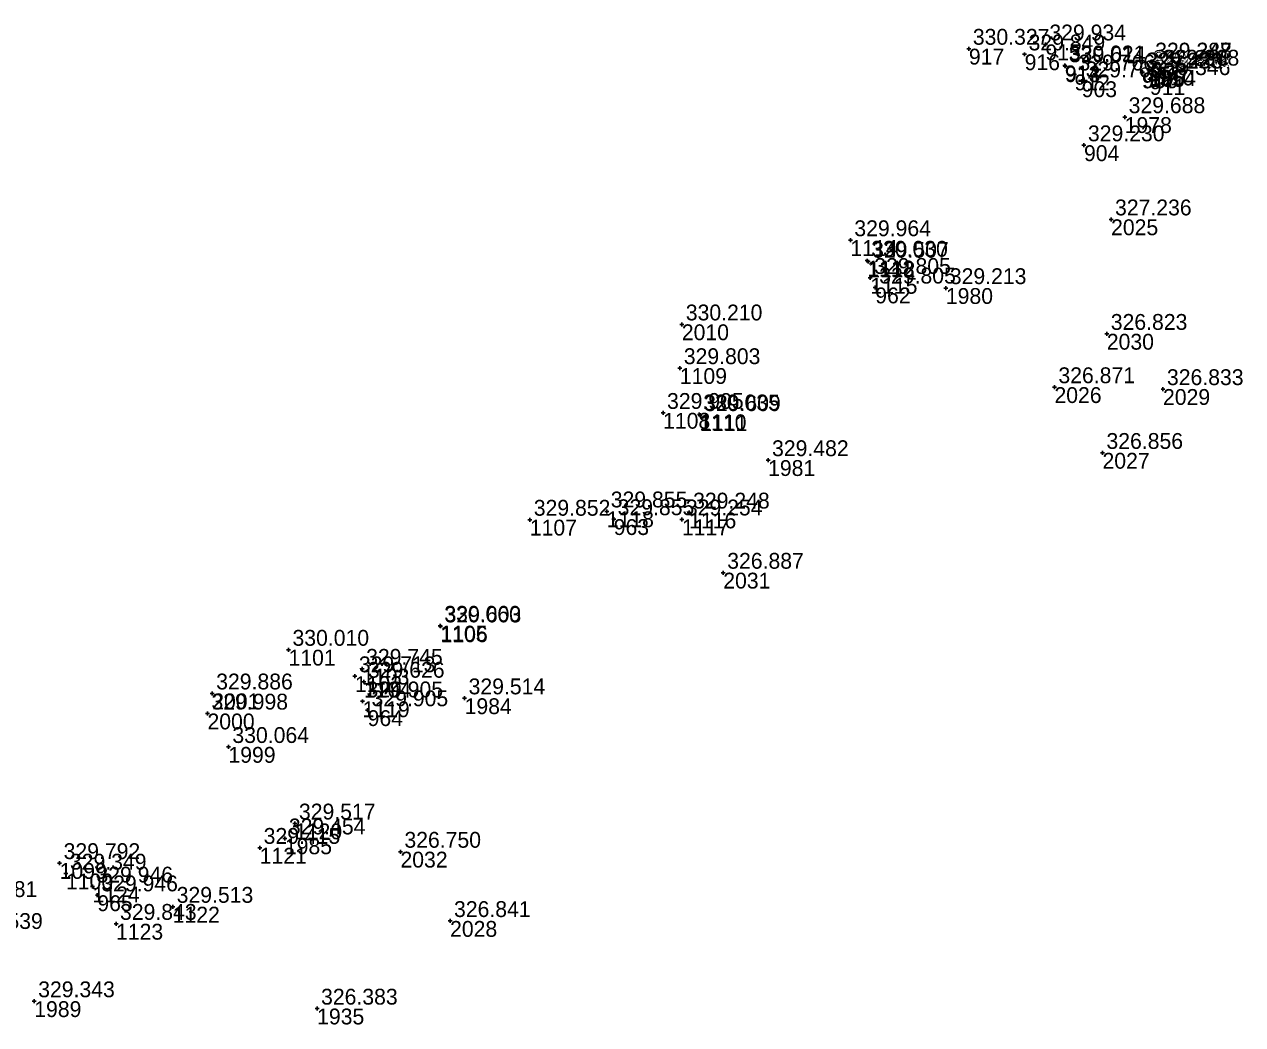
# Model space of a CAD drawing. Extents: x -829398 to -819400, y -1074439 to -1067977.
# Drawn here: x -822578.1 to -822485.9, y -1072748.2 to -1072672.4 of the extents above; entities that cross this region are included whole.
import ezdxf

# ---------------------------------------------------------------- set-up
doc = ezdxf.new("R2010")
doc.units = 0
for name, color, linetype in [('Vrstva 60', 7, 'Continuous'), ('Vrstva 61', 7, 'Continuous'), ('Čísla bodů_doměření_2012', 7, 'Continuous')]:
    doc.layers.add(name, color=color, linetype=linetype)

# ---------------------------------------------------------------- blocks, each defined once
blk = doc.blocks.new('BOD')
at = {"layer": 'Čísla bodů_doměření_2012'}
for p, q in [((-0.15, 0), (0.15, 0)), ((0, -0.15), (0, 0.15))]:
    blk.add_line(p, q, dxfattribs=at)

msp = doc.modelspace()

# ---------------------------------------------------------------- block references
at = {"layer": 'Vrstva 60'}
for p in [(-822500.818, -1072673.94), (-822506.614, -1072674.267), (-822502.392, -1072674.692), (-822499.351, -1072675.532), (-822499.33, -1072675.593), (-822492.808, -1072675.318), (-822492.806, -1072675.31), (-822492.241, -1072675.848), (-822498.616, -1072676.218), (-822498.07, -1072676.735), (-822493.514, -1072676.07), (-822493.462, -1072676.054), (-822492.982, -1072675.879), (-822492.942, -1072675.957), (-822492.91, -1072676.566), (-822494.814, -1072679.451), (-822497.899, -1072681.58), (-822495.847, -1072687.193), (-822515.587, -1072688.769), (-822514.308, -1072690.322), (-822514.24, -1072690.397), (-822514.078, -1072691.627), (-822513.703, -1072692.354), (-822508.355, -1072692.399), (-822528.349, -1072695.147), (-822496.17, -1072695.864), (-822528.5, -1072698.46), (-822500.134, -1072699.904), (-822491.915, -1072700.048), (-822529.768, -1072701.851), (-822527.024, -1072701.966), (-822526.959, -1072702.018), (-822496.496, -1072704.881), (-822521.818, -1072705.431), (-822539.859, -1072709.943), (-822534.032, -1072709.313), (-822533.507, -1072709.902), (-822528.342, -1072709.921), (-822527.794, -1072709.399), (-822525.211, -1072713.958), (-822546.637, -1072717.973), (-822546.61, -1072718.022), (-822558.13, -1072719.793), (-822553.103, -1072721.798), (-822552.552, -1072721.234), (-822552.415, -1072722.214), (-822563.906, -1072723.101), (-822552.527, -1072723.702), (-822544.795, -1072723.472), (-822564.267, -1072724.627), (-822552.142, -1072724.375), (-822562.68, -1072727.156), (-822557.642, -1072732.954), (-822560.313, -1072734.798), (-822558.405, -1072734.082), (-822549.655, -1072735.093), (-822575.461, -1072735.951), (-822574.983, -1072736.749), (-822572.971, -1072737.729), (-822572.607, -1072738.394), (-822566.899, -1072739.263), (-822545.899, -1072740.34), (-822571.191, -1072740.554), (-822577.384, -1072746.418), (-822555.966, -1072746.976)]:
    msp.add_blockref('BOD', p, dxfattribs=at)

# ---------------------------------------------------------------- texts
for s, p in [('917', (-822506.614, -1072675.467)), ('916', (-822502.392, -1072675.892)), ('915', (-822500.818, -1072675.14)), ('914', (-822499.351, -1072676.732)), ('913', (-822499.33, -1072676.793)), ('909', (-822492.808, -1072676.518)), ('908', (-822492.806, -1072676.51)), ('912', (-822498.616, -1072677.418)), ('907', (-822493.514, -1072677.27)), ('906', (-822493.462, -1072677.254)), ('905', (-822492.942, -1072677.157)), ('1854', (-822492.982, -1072677.079)), ('911', (-822492.91, -1072677.766)), ('910', (-822492.241, -1072677.048)), ('903', (-822498.07, -1072677.935)), ('1978', (-822494.814, -1072680.651)), ('904', (-822497.899, -1072682.78)), ('2025', (-822495.847, -1072688.393)), ('1114', (-822515.587, -1072689.969)), ('1113', (-822514.308, -1072691.522)), ('1112', (-822514.24, -1072691.597)), ('1115', (-822514.078, -1072692.827)), ('962', (-822513.703, -1072693.554)), ('1980', (-822508.355, -1072693.599)), ('2010', (-822528.349, -1072696.347)), ('2030', (-822496.17, -1072697.064)), ('1109', (-822528.5, -1072699.66)), ('2026', (-822500.134, -1072701.104)), ('2029', (-822491.915, -1072701.248)), ('1108', (-822529.768, -1072703.051)), ('1110', (-822527.024, -1072703.166)), ('1111', (-822526.959, -1072703.218)), ('2027', (-822496.496, -1072706.081)), ('1981', (-822521.818, -1072706.631)), ('1118', (-822534.032, -1072710.513)), ('1116', (-822527.794, -1072710.599)), ('1107', (-822539.859, -1072711.143)), ('963', (-822533.507, -1072711.102)), ('1117', (-822528.342, -1072711.121)), ('2031', (-822525.211, -1072715.158)), ('1105', (-822546.637, -1072719.173)), ('1106', (-822546.61, -1072719.222)), ('1101', (-822558.13, -1072720.993)), ('1102', (-822553.103, -1072722.998)), ('1103', (-822552.552, -1072722.434)), ('1104', (-822552.415, -1072723.414)), ('2001', (-822563.906, -1072724.301)), ('1119', (-822552.527, -1072724.902)), ('1984', (-822544.795, -1072724.672)), ('964', (-822552.142, -1072725.575)), ('2000', (-822564.267, -1072725.827)), ('1999', (-822562.68, -1072728.356)), ('1120', (-822557.642, -1072734.154)), ('1985', (-822558.405, -1072735.282)), ('1121', (-822560.313, -1072735.998)), ('2032', (-822549.655, -1072736.293)), ('1099', (-822575.461, -1072737.151)), ('1100', (-822574.983, -1072737.949)), ('1124', (-822572.971, -1072738.929)), ('965', (-822572.607, -1072739.594)), ('1122', (-822566.899, -1072740.463)), ('1123', (-822571.191, -1072741.754)), ('2028', (-822545.899, -1072741.54)), ('1989', (-822577.384, -1072747.618)), ('1935', (-822555.966, -1072748.176))]:
    msp.add_text(s, height=1.2, dxfattribs=at).set_placement(p)
at = {"layer": 'Vrstva 61'}
for s, p in [('330.327', (-822506.314, -1072673.967)), ('329.934', (-822500.518, -1072673.64)), ('329.849', (-822502.092, -1072674.392)), ('329.387', (-822492.508, -1072675.018)), ('329.248', (-822492.506, -1072675.01)), ('330.021', (-822499.051, -1072675.232)), ('329.614', (-822499.03, -1072675.293)), ('329.766', (-822498.316, -1072675.918)), ('329.233', (-822493.214, -1072675.77)), ('329.420', (-822493.162, -1072675.754)), ('329.396', (-822492.682, -1072675.579)), ('329.402', (-822492.642, -1072675.657)), ('329.368', (-822491.941, -1072675.548)), ('329.766', (-822497.77, -1072676.435)), ('329.346', (-822492.61, -1072676.266)), ('329.688', (-822494.514, -1072679.151)), ('329.230', (-822497.599, -1072681.28)), ('327.236', (-822495.547, -1072686.893)), ('329.964', (-822515.287, -1072688.469)), ('330.030', (-822514.008, -1072690.022)), ('329.507', (-822513.94, -1072690.097)), ('329.805', (-822513.778, -1072691.327)), ('329.805', (-822513.403, -1072692.054)), ('329.213', (-822508.055, -1072692.099)), ('330.210', (-822528.049, -1072694.847)), ('326.823', (-822495.87, -1072695.564)), ('329.803', (-822528.2, -1072698.16)), ('326.871', (-822499.834, -1072699.604)), ('326.833', (-822491.615, -1072699.748)), ('329.905', (-822529.468, -1072701.551)), ('330.035', (-822526.724, -1072701.666)), ('329.609', (-822526.659, -1072701.718)), ('326.856', (-822496.196, -1072704.581)), ('329.482', (-822521.518, -1072705.131)), ('329.855', (-822533.732, -1072709.013)), ('329.248', (-822527.494, -1072709.099)), ('329.852', (-822539.559, -1072709.643)), ('329.855', (-822533.207, -1072709.602)), ('329.254', (-822528.042, -1072709.621)), ('326.887', (-822524.911, -1072713.658)), ('330.060', (-822546.337, -1072717.673)), ('329.603', (-822546.31, -1072717.722)), ('330.010', (-822557.83, -1072719.493)), ('329.745', (-822552.252, -1072720.934)), ('329.713', (-822552.803, -1072721.498)), ('329.626', (-822552.115, -1072721.914)), ('329.886', (-822563.606, -1072722.801)), ('329.905', (-822552.227, -1072723.402)), ('329.514', (-822544.495, -1072723.172)), ('329.998', (-822563.967, -1072724.327)), ('329.905', (-822551.842, -1072724.075)), ('330.064', (-822562.38, -1072726.856)), ('329.517', (-822557.342, -1072732.654)), ('329.454', (-822558.105, -1072733.782)), ('329.415', (-822560.013, -1072734.498)), ('326.750', (-822549.355, -1072734.793)), ('329.792', (-822575.161, -1072735.651)), ('329.349', (-822574.683, -1072736.449)), ('329.946', (-822572.671, -1072737.429)), ('329.881', (-822582.955, -1072738.526)), ('329.946', (-822572.307, -1072738.094)), ('329.513', (-822566.599, -1072738.963)), ('329.843', (-822570.891, -1072740.254)), ('326.841', (-822545.599, -1072740.04)), ('329.539', (-822582.539, -1072740.945)), ('329.343', (-822577.084, -1072746.118)), ('326.383', (-822555.666, -1072746.676))]:
    msp.add_text(s, height=1.2, dxfattribs=at).set_placement(p)

doc.saveas('drawing.dxf')
